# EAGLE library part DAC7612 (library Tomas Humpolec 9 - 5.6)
Dual, 12-Bit Serial Input DIGITAL-TO-ANALOG CONVERTER FEATURES LOW POWER: 3.7mW FAST SETTLING: 7ms to 1 LSB 1mV LSB WITH 4.095V FULL-SCALE RANGE COMPLETE WITH REFERENCE 12-BIT LINEARITY AND MONOTONICITY OVER INDUSTRIAL TEMP RANGE 3-WIRE INTERFACE: Up to 20MHz Clock SMALL PACKAGE: 8-Lead SOIC APPLICATIONS PROCESS CONTROL DATA ACQUISITION SYSTEMS CLOSED-LOOP SERVO-CONTROL PC PERIPHERALS PORTABLE INSTRUMENTATION
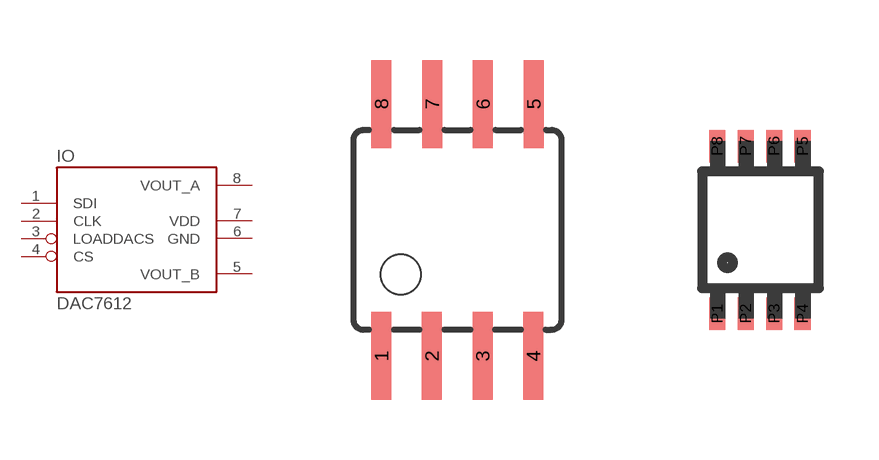
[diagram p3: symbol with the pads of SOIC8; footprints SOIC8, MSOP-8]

Designator prefix IO

## DAC7612SOIC8  [SOIC8]
1  SDI
2  CLK
3  LOADDACS
4  CS
5  VOUT_B  out
6  GND  pwr
7  VDD  pwr
8  VOUT_A  out

## DAC7612MSOP8  [MSOP-8]
P1  SDI
P2  CLK
P3  LOADDACS
P4  CS
P5  VOUT_B  out
P6  GND  pwr
P7  VDD  pwr
P8  VOUT_A  out

## Footprint SOIC8 (pad centres in mm)
Wide Plastic Gull Wing Small Outline Package
smd 0.5 x 2.2: 1 -1.905,-3.154; 2 -0.645,-3.154; 3 0.625,-3.154; 4 1.895,-3.154; 5 1.905,3.154; 6 0.635,3.154; 7 -0.635,3.154; 8 -1.905,3.154

## Footprint MSOP-8 (pad centres in mm)
Small Outline Package SO-8, CASE 751
smd 0.406 x 0.813: P1 -2.159,-2.54; P2 -1.448,-2.54; P3 -0.737,-2.54; P4 -0.025,-2.54; P5 -0.025,1.651; P6 -0.737,1.651; P7 -1.448,1.651; P8 -2.159,1.651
